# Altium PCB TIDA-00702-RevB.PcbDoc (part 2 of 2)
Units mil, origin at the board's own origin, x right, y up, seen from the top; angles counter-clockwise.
Board outline 3789.41 x 3228.35 mil, 2 copper layers (Top Layer, Bottom Layer), stack 62 mil thick; 129 components, 54 nets, 298 pads, 91 vias.
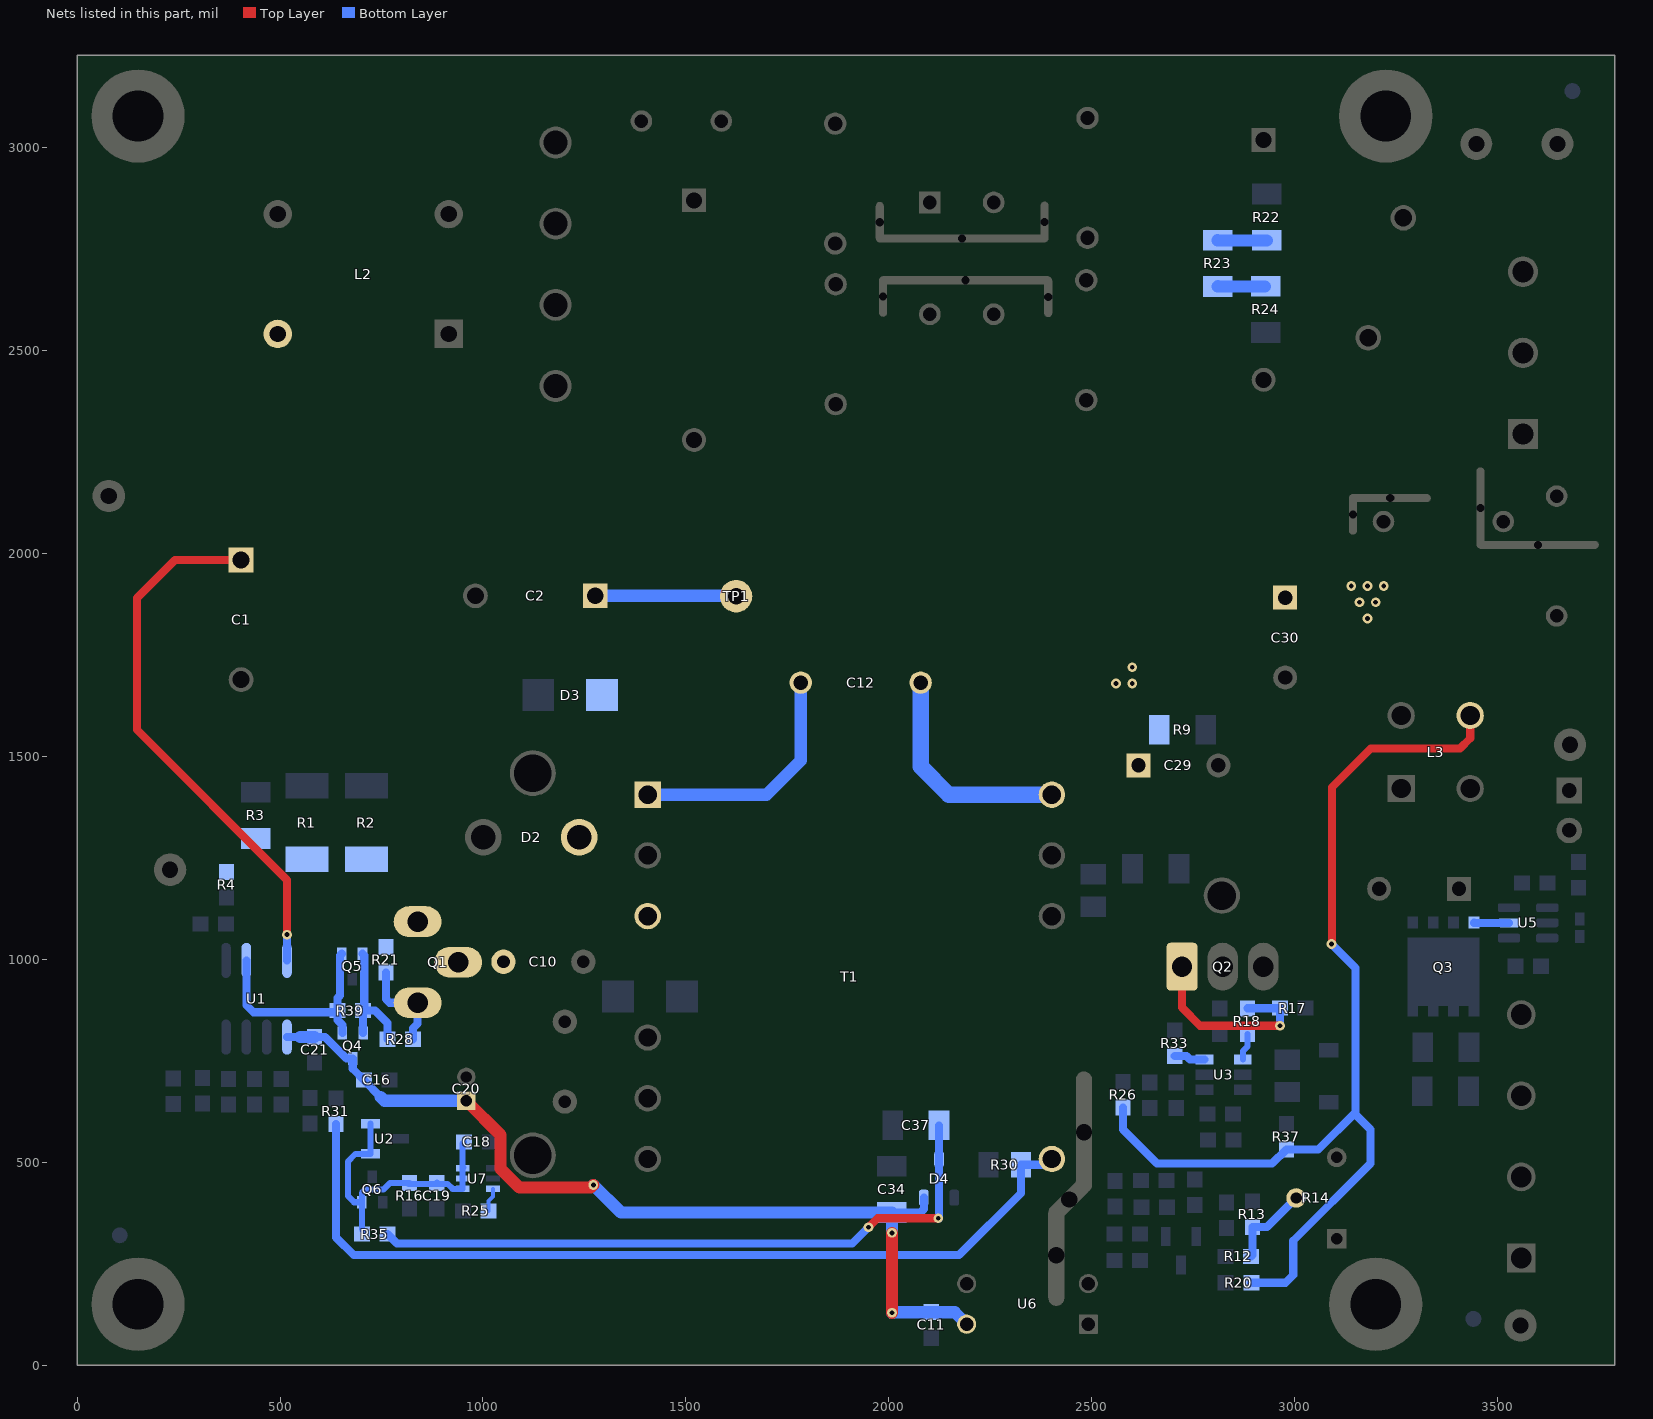
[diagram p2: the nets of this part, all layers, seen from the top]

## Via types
v1: diameter 24, hole 12, Top Layer to Bottom Layer, tented both sides, 82 vias
v2: diameter 20, hole 10, Top Layer to Bottom Layer, 9 vias

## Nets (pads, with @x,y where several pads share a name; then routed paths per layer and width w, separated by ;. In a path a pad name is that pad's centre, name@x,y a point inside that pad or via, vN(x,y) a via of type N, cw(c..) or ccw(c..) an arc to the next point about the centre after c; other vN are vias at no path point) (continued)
NetQ1_1: Q1.1 R21.2 R28.2 | length 241.8
  Bottom Layer w20: R21.2@761,967.5 761,902 770,893 Q1.1@839,893 839,841.47 827.78,830.24 R28.2@827.78,803.04
NetQ1_3: Q1.3 R1.2 R2.1 R3.2 R4.2 R21.1
NetQ2_1: Q2.1 R17.1 R18.2 | length 485.2
  Top Layer w20: Q2.1@2723,982 2723,881 2767.5,836.5 v1(2964.5,836.5)
  Bottom Layer w20: R18.2@2884,879.5 2964,879.5 R17.1@2964.5,880 v1(2964.5,836.5)
NetQ3_4: Q3.4 U5.5 | length 86.3
  Bottom Layer w20: Q3.4@3442.38,1090.34 3442.72,1090 U5.5@3528.51,1090
NetQ4_1: Q4.1 Q5.1 R39.1 U1.6 | length 542.7
  Bottom Layer w20: U1.6@417,997.49 417,887 434.18,869.82 R39.1@637.32,869.82 ; Q5.1@652,1014 647.59,1009.59 647.59,911 641.5,904.91 R39.1@641.5,874 641.5,850.5 653.41,838.59 Q4.1@653.41,818.5
NetQ4_2: Q4.2 Q5.2 R28.1 R39.2 | length 311.7
  Bottom Layer w20: Q5.2@703.18,1014 707.59,1009.59 707.59,877.09 R39.2@704.5,874 ; Q4.2@704.5,818.59 R39.2@704.5,874 ; R28.1@764.78,803.04 764.78,843.22 734,874 R39.2@704.5,874
NetR12_1: R12.1 R13.2 R14.2 | length 211.4
  Bottom Layer w20: R12.1@2892.76,268 2896.27,271.5 R13.2@2896.27,340.5 2932.57,340.5 R14.2@3004.06,412
NetR18_1: R18.1 U3.4 | length 67.8
  Bottom Layer w15: U3.4@2872.71,753.4 2872.71,773.71 2884,785 R18.1@2884,816.5
NetR22_2: R22.2 R23.1 | length 121.1
  Bottom Layer w30: R23.1@2810.64,2772.14 2810.81,2771.97 R22.2@2931.64,2771.97
NetR23_2: R23.2 R24.1 | length 118.5
  Bottom Layer w30: R23.2@2811.81,2659.14 R23.2@2810.64,2657.97 R24.1@2927.47,2657.97
NetR25_1: R25.1 U7.3 | length 59.1
  Bottom Layer w10: R25.1@1013.41,379.98 1013.41,404.74 1024.67,416 U7.3@1024.67,434.39
NetR30_1: R30.1 R31.2 T1.7 | length 2201.1
  Bottom Layer w20: R31.2@637.8,593.99 637.8,314.73 681.53,271 2173.4,271 2326,423.6 R30.1@2326,494 2387.85,494 T1.7@2402.03,508.18
NetR33_1: R33.1 U3.3 | length 76.6
  Bottom Layer w20: R33.1@2705,761.5 2733.9,761.5 2742,753.4 U3.3@2778.22,753.4
TM2: C10.2 D2.1 Q1.2 T1.3
V2.5V: C18.1 C19.2 Q6.2 R16.2 R35.2 U2.1 U2.2 U7.4 U7.5 U7.6 | length 751.6
  Bottom Layer w15: R35.2@707.94,329.13 701.68,335.39 Q6.2@701.68,401.49 ; U2.2@722.83,595.38 U2.1@722.83,520.58 685.86,520.58 667,501.72 667,417 682.51,401.49 Q6.2@701.68,401.49 ; R16.2@817.1,446.48 C19.2@883.27,446.48 ; R16.2@819.27,448.48 770.76,448.48 755.27,432.98 710.27,432.98 701.68,424.39 Q6.2@701.68,401.49 ; C19.2@886.27,449.48 885.77,448.98 C19.2@883.27,446.48 ; U7.6@951.77,487.48 U7.6@949.86,485.57 ; C18.1@953.77,549.98 949.86,546.08 U7.6@949.86,485.57 ; C19.2@883.27,446.48 886.27,446.48 913.04,446.48 925.12,434.39 U7.4@949.86,434.39 U7.5@949.86,459.98 U7.6@949.86,485.57
VCC: C37.1 D4.3 R35.1 | length 1621.4
  Top Layer w20: v1(1950,340) 1972,362 v1(2122,362)
  Bottom Layer w20: R35.1@764.9,323.09 787.99,300 1910,300 v1(1950,340) ; v1@2124,362 D4.3@2124,507.24 2124,590.91 C37.1@2124.09,591
VDCBUS+: C1.1 C2.1 C12.1 D3.1 L2.2 T1.1 TP1.1 U1.8 | length 2300.1
  Top Layer w20: C1.1@404,1984.64 240.64,1984.64 147,1891 147,1566 517,1196 v1(517,1061)
  Bottom Layer w20: U1.8@517,997.49 v1(517,1061)
  Bottom Layer w30: C2.1@1276.64,1896 1616,1896 TP1.1@1626,1906 ; T1.1@1405.97,1405.82 1698.82,1405.82 1783.36,1490.36 C12.1@1783.36,1682
VDD: C11.1 C16.1 C20.1 C21.1 C34.1 D4.2 Q4.3 U1.1 U6.4 | length 2293.4
  Top Layer w30: C20.1@959,651.47 1043.54,566.93 1043.54,484.03 1090.09,437.48 1265.48,437.48 v1(1272,444) ; v1(2008,129) v1(2008,326)
  Bottom Layer w20: U1.1@517,808.51 549.51,808.51 ; C21.1@585,808.5 610.39,808.5 663.39,755.5 Q4.3@679,755.5 679,730.5 C16.1@706.5,703 706.5,702.15 747.83,660.83 ; C34.1@2008,375.91 2077.91,375.91 2086.6,384.6 D4.2@2086.6,412.76
  Bottom Layer w30: 549.53,808.5 C21.1@585,808.5 ; 747.83,660.83 757.18,651.47 C20.1@959,651.47 ; v1(1272,444) 1340.09,375.91 C34.1@2008,375.91 v1(2008,326) ; v1(2008,129) 2009.5,130.5 C11.1@2105,130.5 2162.5,130.5 U6.4@2192,101
VOUT: C12.2 C29.1 C30.1 L3.4 R9.2 R20.1 R26.1 R37.1 T1.12 | length 3155.9
  Top Layer w20: v1(3091,1038) 3091,1036 3092.16,1037.16 3092.16,1424.16 3188,1520 3408,1520 3433.04,1545.04 L3.4@3433.04,1600.96
  Bottom Layer w20: R26.1@2577.47,634.5 2577.47,580.53 2661.5,496.5 2945,496.5 R37.1@2980,531.5 3058.5,531.5 3150,623 ; R20.1@2893.5,203 2978,203 2997,222 2997,306.5 3187,496.5 3187,581 3150,618 3150,623 ; v1(3091,1038) 3150,979 3150,623
  Bottom Layer w40: C12.2@2078.64,1682 2078.64,1475.36 2148.18,1405.82 T1.12@2402.03,1405.82
  other v1: 2560,1680 2600,1680 2600,1720 3180,1840 3160,1880 3200,1880 3140,1920 3180,1920 3220,1920
pads on no net: FID1.1 FID2.1 FID3.1 H1.1 H2.1 H3.1 H4.1 HS2.1@1123,1459.06 R14.1 T1.2 T1.8 T1.9 T1.11

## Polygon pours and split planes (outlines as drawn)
GND-3 on Bottom Layer "Bottom Layer-No Net" (solid, remove dead copper, pour order 72): 3102,1325 3102,1359 3102,1443 3114,1455 3235,1455 3296,1455 3301,1450 3302,1449 3302,1422 3302,1246 3279,1223 3249,1193 3249,842 3268,823 3342,823 3352,813 3352,619 3448,523 3592,523 3632,483 3632,243 3603,214 3523,214 3345,214 3299,260 3218,341 3218,394 3218,615 3180.26,652.74 3166,667 3166,719 3166,1020 3102,1084 3102,1098 3102,1326
NetC17_1 on Bottom Layer "Bottom Layer-No Net" (solid, remove dead copper, pour order 70): 3274,1078 3274,1163 3284,1173 3325,1214 3384,1214 3401,1231 3401,1268 3401,1438 3423,1460 3452,1460 3511,1460 3513,1458 3526,1445 3526,1388 3526,1213 3511,1198 3409,1096 3409,1079 3409,1077 3406,1074 3405.72,1073.72 3394.72,1073.72 3276.28,1073.72 3274,1076
GND-2 on Bottom Layer "Bottom Layer-No Net" (solid, remove dead copper, pour order 68): 2531,56 2531,835 2552,856 2847,856 2860,869 2883,892 2883,1046.35 2883,1072 2849,1106 2767,1188 2742,1188 2692,1188 2679,1201 2679,1266 2705,1292 2753,1340 2753,1401 2753,1607 2878,1732 3021,1732 3277,1732 3298,1711 3298,1612 3298,1583 3289,1574 3278,1563 3266,1563 3076,1563 3063,1550 3063,1547 3063,975 3125,913 3124,912 3124,319 3032,227 3032,67 3006,41 2546,41
VOUT on Bottom Layer "Bottom Layer-No Net" (solid, remove dead copper, pour order 66): 2368,1533 2368,1381 2382,1367 2632,1367 2668,1367 2694,1393 2694,1489 2694,1628 2861,1795 3144,1795 3234,1795 3251,1812 3251,1932 3236,1947 3139,1947 2781,1947 2736,1902 2368,1534
GND on Bottom Layer "Bottom Layer-No Net" (solid, remove dead copper, pour order 64): 549,1659 549,1633 549,1629 551,1627 553,1625 553,1624 553,1580 549,1576 548,1575 548,1564 548,1497 551,1494 564.87,1480.13 784,1480.13 793.13,1480.13 797,1484 797,1544 797,1613 858,1674 858,1695 854,1699 844,1709 615,1709 561,1709 549,1697
GND on Bottom Layer "Bottom Layer-No Net" (solid, remove dead copper, pour order 63): 72,2906 516,2906 527,2895 533,2889 533,2861 533,2794 522,2783 517,2778 459,2778 306,2778 222,2694 222,1893 272,1843 307,1808 419,1808 837,1808 955,1926 1005,1926 1019,1912 1019,1889 1019,1871 1019,1835 813,1629 613,1629 118,1629 58,1689 46,1701 46,1996 46,2880
VDCBUS+ on Bottom Layer "Bottom Layer-No Net" (solid, remove dead copper, pour order 62): 367,2555 367,2093 367,1997 367,1955 376,1946 384,1938 433,1938 741,1938 848,2045 1108,2045 1204,1949 1246,1907 1246,1879 1246,1621 1281,1586 1364,1503 1364,1415 1364,1376 1370,1370 1373,1367 1513,1367 1515,1367 1538,1390 1539,1391 1539,1436 1539,1760 1518,1781 1463,1836 1380,1836 1340,1836 1313,1863 1310,1866 1310,2024 1178,2156 1146,2188 954,2188 578,2188 558,2208 558,2563 538,2583 437,2583 395,2583
NetBR1_1 on Bottom Layer "Bottom Layer-No Net" (solid, remove dead copper, pour order 60): 1173,2372 1200,2372 1204,2376 1219,2391 1219,2404 1219,2441 1209,2451 1208,2452 1178,2452 1027,2452 998,2481 992,2487 992,2572 979,2585 853,2585 840,2572 840,2555 840,2353 856,2337 863,2330 979,2330 1072,2330 1114,2372
NetBR1_4 on Bottom Layer "Bottom Layer-No Net" (solid, remove dead copper, pour order 61): 1173,3054 1200,3054 1204,3050 1219,3035 1219,3022 1219,2985 1209,2975 1208,2974 1178,2974 1027,2974 998,2945 992,2939 992,2846 992,2816 976,2800 920,2800 879,2800 862,2800 858,2800 854,2800 841,2813 840,2814 840,2871 840,3073 856,3089 863,3096 979,3096 1072,3096 1114,3054
NetBR1_2 on Bottom Layer "Bottom Layer-No Net" (solid, remove dead copper, pour order 57): 1148,2652 1224,2652 1374,2652 1396,2630 1460.36,2565.64 1460.36,2485 1460.36,2352.64 1485,2328 1553,2328 1758,2328 1794,2364 1829,2399 1855,2399 1947,2399 1985,2437 2046,2498 2046,2577 2046,2603 2055,2612 2061,2618 2094,2618 2121,2618 2126,2613 2133,2606 2133,2584 2133,2438 1996,2301 1974,2279 1855,2279 1849,2279 1804,2234 1777,2207 1534,2207 1427,2207 1345,2289 1344,2290 1344,2430 1344,2484 1255,2573 1183,2573 1146,2573 1135,2584 1135,2642 1145,2652
NetC4_1 on Bottom Layer "Bottom Layer-No Net" (solid, remove dead copper, pour order 56): 1485,2899 1482,2896 1482,2872 1482,2843 1493,2832 1545,2832 1661,2948 1706,2993 1787,2993 1919,2993 2073,2839 2077,2835 2125,2835 2131,2841 2131,2953 1969,3115 1866,3115 1583,3115 1556,3088 1554,3086 1554,2968 1492,2906
NetQ1_3 on Bottom Layer "Bottom Layer-No Net 1" (solid, remove dead copper, pour order 45): 724.23,1067.77 724.23,1017.77 733,1009 792.89,1009 798,1014.11 798,1051 802,1055 879,1055 899,1075 899,1160 879,1180 799.24,1180 795,1184.24 795,1319 781,1333 348,1333 337,1322 337,1203 345,1195 597,1195
GND on Bottom Layer "Bottom Layer-No Net 6" (solid, remove dead copper, pour order 53): 87,1576 49,1538 49,1042 63,1028 280,1028 303.5,1051 304,1337 342,1376 775,1376 797,1398 797,1544 765,1576
GND on Bottom Layer "Bottom Layer-No Net 1" (solid, remove dead copper, pour order 46): 996,571 996,514 996,467 1000,463 1010,453 1032,453 1163,453 1174,464 1180,470 1180,512 1180,552 1169,563 1159,573 1132,573 1000,573 996,569
NetBR1_3 on Bottom Layer "Bottom Layer-No Net 1" (solid, remove dead copper, pour order 44): 1242,2852 1342,2952 1342,3089 1353,3100 1427,3100 1436,3091 1436,2939 1268,2771 1149,2771 1138,2782 1138,2840 1150,2852
TM2 on Bottom Layer "Bottom Layer-No Net 2" (solid, remove dead copper, pour order 37): 914.39,1028.04 899.04,1028.04 880,1009 880,969 893,956 1053,956 1189,1092 1337,1092 1356,1073 1438,1073 1445,1080 1445,1138 1438,1145 1360,1145 1289,1216 1289,1327 1269,1347 1211,1347 1191,1327 1191,1273 946,1028 931,1028
GND-3 on Bottom Layer "Bottom Layer-No Net 7" (solid, remove dead copper, pour order 39): 3594,1098 3584,1088 3584,1003 3584,970 3590,964 3592,962 3636.78,962 3718,962 3727,971 3731,975 3731,1041 3731,1071.26 3724.26,1078 3699,1078 3678,1078 3670,1086 3653,1103 3646,1103 3599,1103 3594,1098
NetC32_1 on Bottom Layer "Bottom Layer-No Net 8" (solid, remove dead copper, pour order 43): 3272,1049 3272,860 3276,856 3279,853 3381,853 3386,853 3393,846 3398,841 3398,816 3398,641 3406,633 3411.64,627.36 3466.49,627.36 3610.36,627.36 3625,642 3629,646 3629,797 3629,894 3618,905 3617,906 3561,906 3491,906 3477,920 3469,928 3469,1009 3469,1036 3451,1054 3297,1054 3277,1054 3272,1049
GND on Bottom Layer "Bottom Layer-No Net 1" (solid, remove dead copper, pour order 51): 38,401 56,383 177,383 312,248 312,78 339,51 804,51 810,45 2082.5,45 2107,69.5 2107,522.3 2107,494 2050,551 2045.5,555.5 2045.5,636.5 2030,652 1978,652 1873,547 1185,547 1155.95,576.05 1148.93,576.07 1105,576 1077.64,576.07 1062,590 1062,696 1010,748 808,748 725.59,830.41 725.59,915.41 715,926 410,926 380,956 380,1103.27 355.27,1128 59,1128 38,1107
NetC28_2 on Bottom Layer "Top Layer-No Net 3" (solid, remove dead copper, pour order 48): 2363,1140 2363,961 2363,946 2363,935 2368,930 2385,913 2438,913 2615.99,913 2626.13,923.15 2638,935.01 2638,1031 2638,1047 2653,1062 2732,1062 2769,1062 2782,1049 2787,1044 2787,1032 2787,939.15 2803,923.15 2803.15,923 2845,923 2860,938 2861,939 2861,973 2861,1053 2821.95,1092.05 2756,1158 2727,1158 2381,1158 2363,1140
NetF1_2 on Bottom Layer "Bottom Layer-No Net" (solid, remove dead copper, pour order 38): 3610,3054.65 3607,3051.65 3607,2969.65 3607,2785.65 3592,2770.65 3576,2754.65 3555,2754.65 3527,2754.65 3524,2751.65 3517,2744.65 3517,2722.65 3517,2669.65 3522,2664.65 3531,2655.65 3564,2655.65 3720,2655.65 3733,2668.65 3738,2673.65 3738,2794.65 3738,3052.65 3730,3060.65 3616,3060.65
GNDE on Bottom Layer "Bottom Layer-No Net" (solid, remove dead copper, pour order 42): 3520,2329.65 3520,2168.65 3499,2147.65 3489,2137.65 3489,2083.65 3489,2066.65 3494,2061.65 3502,2053.65 3530,2053.65 3560,2053.65 3561,2053.65 3568,2060.65 3572,2064.65 3572,2093.65 3572,2101.65 3580,2109.65 3581,2110.65 3631,2110.65 3681,2110.65 3684,2113.65 3685,2114.65 3685,2143.65 3685,2309.65 3685,2321.65 3674,2332.65 3672,2334.65 3585,2334.65 3524,2334.65 3520,2330.65
NetC3_1 on Bottom Layer "M9 Title Sheet-No Net" (solid, remove dead copper, pour order 54): 3421,3051.65 3410,3040.65 3410,3022.65 3410,2980.65 3401,2971.65 3288,2858.65 3270,2858.65 3255,2858.65 3243,2870.65 3203,2910.65 3170,2910.65 3096,2910.65 2950,3056.65 2894,3056.65 2850,3056.65 2846,3060.65 2791,3115.65 2492,3115.65 2394,3115.65 2236,2957.65 2231,2952.65 2231,2883.65 2231,2847.65 2240,2838.65 2242,2836.65 2278,2836.65 2305,2836.65 2309,2840.65 2320,2851.65 2320,2879.65 2320,2888.65 2370,2938.65 2417,2985.65 2747,2985.65 2873,2859.65 2964,2859.65 3045,2778.65 3219,2778.65 3235,2794.65 3237,2796.65 3248,2796.65 3300,2796.65 3311,2785.65 3316,2780.65 3380,2780.65 3490,2890.65 3490,3038.65 3477,3051.65
GND-3 on Top Layer "Bottom Layer-No Net" (solid, remove dead copper, pour order 71): 3102,1325 3102,1359 3102,1443 3114,1455 3235,1455 3296,1455 3301,1450 3302,1449 3302,1422 3302,1246 3279,1223 3249,1193 3249,842 3268,823 3342,823 3352,813 3352,619 3448,523 3592,523 3632,483 3632,243 3603,214 3523,214 3345,214 3299,260 3218,341 3218,394 3218,615 3180.26,652.74 3166,667 3166,719 3166,1020 3102,1084 3102,1098 3102,1326
NetC17_1 on Top Layer "Bottom Layer-No Net" (solid, remove dead copper, pour order 69): 3274,1078 3274,1163 3284,1173 3325,1214 3384,1214 3401,1231 3401,1268 3401,1438 3423,1460 3452,1460 3511,1460 3513,1458 3526,1445 3526,1388 3526,1213 3511,1198 3409,1096 3409,1079 3409,1077 3406,1074 3405.72,1073.72 3394.72,1073.72 3276.28,1073.72 3274,1076
GND-2 on Top Layer "Bottom Layer-No Net" (solid, remove dead copper, pour order 67): 2531,56 2531,835 2552,856 2847,856 2860,869 2883,892 2883,1046.35 2883,1072 2849,1106 2767,1188 2742,1188 2692,1188 2679,1201 2679,1266 2705,1292 2753,1340 2753,1401 2753,1607 2878,1732 3021,1732 3277,1732 3298,1711 3298,1612 3298,1583 3289,1574 3278,1563 3266,1563 3076,1563 3063,1550 3063,1547 3063,975 3125,913 3124,912 3124,319 3032,227 3032,67 3006,41 2546,41
VOUT on Top Layer "Bottom Layer-No Net" (solid, remove dead copper, pour order 65): 2368,1532 2368,1381 2382,1367 2668,1367 2694,1393 2694,1627 2862,1795 3363,1795 3386,1772 3389,1769 3389,1648 3389,1586 3398,1577 3407,1568 3449,1568 3485,1568 3494,1577 3504,1587 3504,1673 3504,1909 3477,1936 3467,1946 3426,1946 2781,1946 2755,1920 2368,1533
NetBR1_4 on Top Layer "Bottom Layer-No Net" (solid, remove dead copper, pour order 58): 1173,3054 1200,3054 1204,3050 1219,3035 1219,3022 1219,2985 1209,2975 1208,2974 1178,2974 1027,2974 998,2945 992,2939 992,2846 992,2816 976,2800 920,2800 879,2800 862,2800 858,2800 854,2800 841,2813 840,2814 840,2871 840,3073 856,3089 863,3096 979,3096 1072,3096 1114,3054
NetBR1_1 on Top Layer "Bottom Layer-No Net" (solid, remove dead copper, pour order 59): 1173,2372 1200,2372 1204,2376 1219,2391 1219,2404 1219,2441 1209,2451 1208,2452 1178,2452 1027,2452 998,2481 992,2487 992,2572 979,2585 853,2585 840,2572 840,2555 840,2353 856,2337 863,2330 979,2330 1072,2330 1114,2372
GND on Top Layer "Bottom Layer-No Net 1" (solid, remove dead copper, pour order 52): 612,1514 612,928 608,924 608,911 621,898 718,898 733,913 733,1167 798,1232 798,1515 788,1525 623,1525
NetBR1_2 on Top Layer "Bottom Layer-No Net 1" (solid, remove dead copper, pour order 49): 1135,2642 1135,2584 1146,2573 1202,2573 1256,2573 1285,2544 1344,2485 1344,2290 1427,2207 1550,2207 1558,2207 1564,2213 1564,2241 1564,2317 1558,2323 1553,2328 1536,2328 1484,2328 1460,2352 1460.36,2352.36 1460.36,2400.43 1460.36,2565.64 1377,2649 1374,2652 1360,2652 1145,2652
NetBR1_3 on Top Layer "Bottom Layer-No Net 1" (solid, remove dead copper, pour order 41): 1242,2852 1342,2952 1342,3089 1353,3100 1427,3100 1436,3091 1436,2939 1268,2771 1149,2771 1138,2782 1138,2840 1150,2852
NetC32_1 on Top Layer "Bottom Layer-No Net 8" (solid, remove dead copper, pour order 40): 3272,1049 3272,860 3276,856 3279,853 3381,853 3386,853 3393,846 3398,841 3398,816 3398,641 3406,633 3411.64,627.36 3466.49,627.36 3610.36,627.36 3625,642 3629,646 3629,797 3629,894 3618,905 3617,906 3561,906 3491,906 3477,920 3469,928 3469,1009 3469,1036 3451,1054 3297,1054 3277,1054 3272,1049
GND on Top Layer "Bottom Layer-No Net 1" (solid, remove dead copper, pour order 50): 38,401 56,383 176,383 312,247 312,78 339,51 804,51 810,45 2082.5,45 2113,75.5 2113,308 2082,339 1285,339 1181,443 1181,544 1149,576 1077.64,576.07 1062,590 1062,696 1010,748 808,748 725.59,830.41 725.59,915.41 715,926 410,926 380,956 380,1103.27 355.27,1128 59,1128 38,1107
NetC28_2 on Top Layer "Top Layer-No Net 3" (solid, remove dead copper, pour order 47): 2363,1140 2363,961 2363,946 2363,935 2368,930 2385,913 2438,913 2615.99,913 2626.13,923.15 2638,935.01 2638,1031 2638,1047 2653,1062 2732,1062 2769,1062 2782,1049 2787,1044 2787,1032 2787,939.15 2803,923.15 2803.15,923 2845,923 2860,938 2861,939 2861,973 2861,1053 2821.95,1092.05 2756,1158 2727,1158 2381,1158 2363,1140
NetC3_2 on Top Layer "M9 Title Sheet-No Net" (solid, remove dead copper, pour order 55): 2230,2616.65 2225,2611.65 2225,2510.65 2225,2497.65 2311,2411.65 2389,2333.65 2401,2321.65 2567,2321.65 2818,2321.65 2866,2369.65 2893,2396.65 2932,2396.65 2956,2396.65 2973,2379.65 3056,2379.65 3175,2498.65 3221,2498.65 3266,2453.65 3376,2453.65 3594,2453.65 3605,2464.65 3605,2518.65 3591,2532.65 3495.85,2532.65 3450.85,2577.65 3440,2577.65 3232,2577.65 3218,2563.65 3103,2563.65 3011,2471.65 2800,2471.65 2451,2471.65 2294,2628.65 2264,2628.65 2242,2628.65

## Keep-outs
Keep-Out Layer:
  lines w10: 25,25 3746,25 3746,3196 25,3196 25,25

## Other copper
Top Layer:
  pour cut-out: 1070,579 1068,577 1068,485 1095,458 1180,458 1186,464 1186,569 1176,579
  text ".Layer_Name" at -358,-858.49 h60
Bottom Layer:
  pour cut-out: 724.23,1028.49 734.99,1038.75 724.23,1049.51
  pour cut-out: 3436,1125 3408.99,1125 3403,1119.01 3403,1082 3395,1074 3417,1074 3428,1085 3428,1117
  text ".Layer_Name" at -358,-858.49 h60

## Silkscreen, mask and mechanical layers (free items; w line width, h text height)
Top Overlay:
  circle w6: c2497,2317 r7
  circle w6: c2661.78,898 r9.22
  circle w6: c939.78,877 r9.22
  circle w6: c3618,1436 r7
  circle w6: c2923,3093.65 r7.07
  circle w6: c3117,2483 r6.32
  circle w10: c3585,2174.65 r8.25
  circle w6: c2526.32,3124.1 r7
  circle w6: c1904.32,3110.1 r7
  circle w6: c1888,2304.64 r7
  circle w6: c1680.46,2876.68 r7
  circle w6: c3683,1809 r6.32
  circle w6: c3184,2045 r6.32
  circle w6: c1710,1678 r7.21
  circle w6: c1288,3170 r8.06
  text ".PRJ_Number" at 515,143 h60
  text ".PCB_Rev" at 1166,141 h60
  text "-" at 1107,139 h60
  text ".Layer_Name" at -358,-858.49 h60
Bottom Overlay:
  circle w6: c1049.27,501.98 r3.16
  circle w6: c680.27,515.98 r4.12
  circle w6: c2746.47,653 r5
  circle w6: c3229,1096 r7.28
  circle w6: c545,767 r7.07
  circle w6: c2664,351 r5.39
  lines w6: 613,1013 613,947 622,938 622,906 ; 2685,535 2693,527 2693,501 2703,491 2719,491 2719,457.93 2722,454.93 2722,426 2714.25,418.25 2714.25,416.2 ; 2783.99,916 2845,916 2853.02,907.98 2856.8,907.98 ; 2878.45,527.8 2878.45,513.55 2893,499 ; 2922,778 2922,786 2928,792 ; 3008,798 3010.53,798 3016.53,804 3019,804 3022,807
  text ".Layer_Name" at -358,-858.49 h60
Top Paste:
  text ".Layer_Name" at -358,-858.49 h60
Bottom Paste:
  text ".Layer_Name" at -358,-858.49 h60
Top Solder:
  text ".Layer_Name" at -358,-858.49 h60
  text ".Layer_Name" at -358,-858.49 h60
Bottom Solder:
  text ".Layer_Name" at -358,-858.49 h60
Drill Guide:
  text ".Layer_Name" at -358,-858.49 h60
M1 Board Outline:
  the board outline again, w10
M2 Board Dimensions:
  rectangle: -810,-410.5 -435,-285.5
  rectangle: -935,-285.5 -810,-160.5
  lines w7: -935,-285.5 65,-285.5 ; -810,-410.5 -810,-160.5 ; -685,-410.5 -685,-160.5 ; -435,-410.5 -435,-160.5 ; -185,-410.5 -185,-160.5 ; -935,-410.5 -935,-160.5 65,-160.5 65,-410.5 -935,-410.5
M3 3D STEP Top:
  text ".Layer_Name" at -358,-858.49 h60
M4 3D STEP Bottom:
  text ".Layer_Name" at -358,-858.49 h60
M5 Assembly Top:
  circle w6: c2101.26,2865.45 r10.33
  circle w6: c3181.69,2532.02 r10.77
  circle w6: c3561,2294 r11.18
  circle w7.87: c2711,1478 r196.85
  circle w7.87: c2978,1792 r196.85
  circle w7.87: c3307,1174 r196.85
  circle w7.87: c3676,1412 r5.83
  circle w7.87: c2719,981 r10.44
  circle w6: c2927,3012.65 r10.77
  circle w6: c3241,2073.72 r10.77
  circle w6: c3649,1866.72 r10.77
  circle w6: c2490,2372.09 r10.77
  circle w6: c2493,3067.36 r10.77
  circle w6: c1871,3053.36 r10.77
  circle w6: c1872,2362.09 r10.77
  circle w6: c1523.36,2864.51 r10.77
  circle w6: c1389,3067.72 r10.77
  circle w6: c918.63,2535.09 r10.77
  circle w6: c1786.36,1675.72 r10.77
  lines w6: 2543,1603 2581,1603 ; 2560,1583 2560,1623 ; 2951,2015 2989,2015 ; 2969,1994 2969,2034 ; 3526,1171 3564,1171 ; 3543,1151 3543,1191
  lines w10: -1227,-930.17 5373,-930.17 ; -1227,-726.83 5375,-726.83 ; -1227,-523.5 -1227,-1133.5 2778,-1133.5 5375,-1133.5 5375,-523.5 -1226.5,-523.5 -1226.5,-1133.5 349,-1133.5 ; 1238,-1133.5 1238,-523.5 ; 2505,-726.83 2505,-523.5 ; 3345,-726.83 3345,-523.5 ; 3967,-1140 3967,-937.17
  text "COMPONENTS MARKED 'DNP' SHOULD NOT BE POPULATED." at 218.5,-318.5 h60
  text "ASSEMBLY VARIANT:" at 218,-434 h60
  text ".VariantName" at 1254,-434 h60
  text "PCB VIEWED FROM TOP SIDE" at -1163.5,-655.67 h60
  text "BOARD #:" at 1313,-655.67 h60
  text ".PRJ_Number" at 1858.5,-655.67 h60
  text "REV:" at 2703,-655.67 h60
  text ".PCB_Rev" at 2994.5,-655.67 h60
  text "SVN REV:" at 3541,-655.67 h60
  text ".VersionControl_RevNumber" at 4047,-655.67 h35
  text ".Layer_Name" at -347,-851 h60
  text "IGNORE ->" at -1163.5,-858.49 h60
  text "PLOT NAME =" at -1163.5,-1064.34 h60
  text ".plot_File_Name" at -358,-1064.34 h60
  text "GENERATED    :" at 1315,-1064.34 h60
  text ".Print_Date" at 2184.5,-1064.34 h60
  text ".Print_Time" at 2913.5,-1064.34 h60
  text "TEXAS INSTRUMENTS" at 4178,-1064.34 h60
M6 Assembly Bottom:
  circle w6: c2186,415 r6
  circle w6: c2682,293 r6.08
  circle w6: c694,564 r8.06
  circle w7.87: c3658,1149 r3.16
  circle w7.87: c516.4,850 r6.4
  circle w7.87: c627,1026 r7.81
  circle w7.87: c629,830 r6.4
  circle w7.87: c758.39,374 r5.39
  lines w10: -1227.5,-727.33 5374.5,-727.33 ; -1225.5,-930.67 5374.5,-930.67 ; 180.5,-1140.5 180.5,-937.67 ; 802.5,-727.33 802.5,-524 ; 1642.5,-727.33 1642.5,-524 ; 2909.5,-1134 2909.5,-524 ; 3798.5,-1134 5374,-1134 5374,-524 -1227.5,-524 -1227.5,-1134 1369.5,-1134 5374.5,-1134 5374.5,-524
  text "COMPONENTS MARKED 'DNP' SHOULD NOT BE POPULATED." at 5167,-318 h60
  text ".VariantName" at 4123,-434 h60
  text "ASSEMBLY VARIANT:" at 5162,-434 h60
  text ".VersionControl_RevNumber" at 100.5,-656.17 h35
  text "SVN REV:" at 606.5,-656.17 h60
  text ".PCB_Rev" at 1153,-656.17 h60
  text "REV:" at 1444.5,-656.17 h60
  text ".PRJ_Number" at 2289,-656.17 h60
  text "BOARD #:" at 2834.5,-656.17 h60
  text "PCB VIEWED FROM BOTTOM SIDE" at 5311,-656.17 h60
  text "IGNORE ->" at 1612.85,-858.49 h60
  text ".Layer_Name" at 958,-863 h60
  text "TEXAS INSTRUMENTS" at -30.5,-1064.84 h60
  text ".Print_Time" at 1234,-1064.84 h60
  text ".Print_Date" at 1963,-1064.84 h60
  text "GENERATED    :" at 2832.5,-1064.84 h60
  text ".plot_File_Name" at 4505.5,-1064.84 h60
  text "PLOT NAME =" at 5311,-1064.84 h60
M9 Title Sheet:
  drawing of 58 lines, arcs and shapes, not listed
  text "1" at -195.16,8036.5 h70
  text "2" at 2300.5,8036.5 h70
  text "3" at 4789.84,8036.5 h70
  text "4" at 7296.51,8036.5 h70
  text "5" at 9795.5,8036.5 h70
  text "6" at 12300.5,8036.5 h70
  text "A" at -1351.5,6893.5 h70
  text "A" at 13448.5,6893.5 h70
  text "B" at -1351.5,4513.5 h70
  text "B" at 13448.5,4513.5 h70
  text "C" at -1351.5,2138.5 h70
  text "C" at 13448.5,2138.5 h70
  text "PROJECT TITLE:" at 10408.5,277.5 h45
  text ".PRJ_Title" at 10458.5,144.17 h70
  text "DESIGNED FOR:" at 10408.5,-23.5 h45
  text ".PRJ_Customer" at 10458.5,-163.5 h70
  text "D" at -1351.5,-231.5 h70
  text "D" at 13448.5,-231.5 h70
  text "FILE NAME:" at 10408.5,-323.5 h45
  text ".PCB_File_Name_No_Path" at 10458.5,-443.5 h70
  text "Texas Instruments (TI) and/or its licensors do not warrant the accuracy or completeness of this specification" at 5439,-605.34 h45
  text "ENGINEER:" at 10408.5,-613.5 h45
  text "LAYOUT BY:" at 11913.5,-613.5 h45
  text "or any information contained therein. TI and/or its licensors do not warrant that this design will meet" at 5394.01,-718 h45
  text ".PRJ_Engineer" at 10458.5,-768.49 h70
  text ".PCB_Layout" at 11964,-768.49 h70
  text "the specifications, will be suitable for your application or fit for any particular purpose, or will operate in" at 5394.01,-830.67 h45
  text "ALTIUM DESIGNER VERSION:" at 11913.5,-923.5 h45
  text "an implementation. TI and/or its licensors do not warrant that the design is production worthy. You should" at 5394.01,-943.33 h45
  text "completely validate and test your design implementation to confirm the system functionality for your application." at 5439,-1056 h45
  text ".print_Scale" at 10458.5,-1056.83 h70
  text ".Application_BuildNumber" at 11964,-1056.83 h70
  text "1" at -195.16,-1263.5 h70
  text "2" at 2300.5,-1263.5 h70
  text "3" at 4789.84,-1263.5 h70
  text "4" at 7296.51,-1263.5 h70
  text "5" at 9795.5,-1263.5 h70
  text "6" at 12300.5,-1263.5 h70
M10 Fab Notes:
  drawing of 228 lines, arcs and shapes, not listed
  text "DESIGN INFORMATION" at 11450.02,6802 h60
  text "(REFER ALSO ARRAY/PANEL PROFILING INFORMATION)" at 11088.46,6640.29 h60
  text "BOARD SIZE" at 10402.46,6636 h60
  text "96.25 MM" at 10864.78,6508.18 h60
  text "X" at 11370.46,6508.18 h60
  text "82 MM" at 11601.78,6508.18 h60
  text "Number of Layers :" at 10805.46,6311 h60
  text "2" at 11900.27,6301 h60
  text "MIN. TRACK WIDTH:" at 10805.46,6172 h60
  text "10" at 11901.7,6172 h60
  text "MIL" at 12056.46,6172 h60
  text "MIN. CLEARANCE:" at 10805.46,6040 h60
  text "MIL" at 12056.46,6040 h60
  text "8" at 11893,6034 h60
  text "10" at 11884,5913 h60
  text "MIN. VIA DRILL SIZE:" at 10805.46,5908 h60
  text "MIL" at 12056.46,5908 h60
  text "MINIMUM ANNULAR RING" at 10476.23,5762 h60
  text "EXTERNAL" at 12497,5760 h60
  text "0.110mm (4.37 MIL)" at 11490,5759 h60
  text "PER" at 10676.23,5644 h60
  text "IPC-D-275 CLASS 2 LEVEL C" at 10896.23,5644 h60
  text "MIL, HOLES" at 12384.46,5531.71 h60
  text "+/-" at 11992,5531 h60
  text "+/-" at 12846,5531 h60
  text "REGISTRATION TOLERANCES:" at 10476.23,5526 h60
  text "METAL" at 11676,5526 h60
  text "5" at 12252.2,5526 h60
  text "3" at 13085.2,5526 h60
  text "MIL" at 13201.46,5526 h60
  text "MATERIAL:" at 10401.46,5316.54 h60
  text "FR-4 High Tg" at 11387.9,5176.21 h60
  text "FR-408" at 10822.46,5167.64 h60
  text "OTHER" at 12310.46,5167.64 h60
  text "X" at 11232,5160 h60
  text "63 MIL (1.6mm) +/-10%" at 11142.56,5004.92 h60
  text "THICKNESS:" at 10476.23,5000.64 h60
  text "X" at 11014.4,5000.64 h60
  text "OTHER" at 12427.46,5000.64 h60
  text "TOLERANCE:" at 10476.23,4842.64 h60
  text "X" at 11315.53,4842.64 h60
  text "ANSI IPC-6012 TYPE 3 CLASS 2" at 11502.48,4842.64 h60
  text "OTHER +/-" at 11502.46,4686.64 h60
  text "BOW & TWIST:" at 10476.23,4529.64 h60
  text "X" at 11315.53,4529.64 h60
  text "ANSI IPC-6012 TYPE 3 CLASS 2" at 11502.48,4529.64 h60
  text "OTHER +/-" at 11502.46,4371.13 h60
  text "COPPER THICKNESS (FINISHED):" at 10401.46,4235.64 h60
  text "X" at 12644,4084 h60
  text "1.4MIL (1oz)" at 11281.46,4082.92 h60
  text "2MIL (1.4oz)" at 12048.46,4082.92 h60
  text "2.8MIL (2oz)" at 12775.46,4082.92 h60
  text "OUTER:" at 10758.46,4078.64 h60
  text "1.4MIL (1oz)" at 11281.46,3925.92 h60
  text "2.8MIL (2oz)" at 12048.46,3925.92 h60
  text "N/A" at 12775,3926.29 h60
  text "INNER SIGNAL:" at 10469.38,3921.64 h60
  text "DRILLING:" at 10401.46,3782.64 h60
  text "REFERENCE:" at 10476.23,3665.64 h60
  text "X" at 11124.46,3665.64 h60
  text "AS SHOWN" at 11311.46,3665.64 h60
  text "X" at 12025.46,3665.64 h60
  text "NC_DRILL FILES" at 12162.46,3665.64 h60
  text "PTH MIN COPPER THICKNESS:" at 10476.23,3507.64 h60
  text "X" at 11826.46,3507.64 h60
  text "1MIL" at 11963.46,3507.64 h60
  text "OTHER" at 12460.46,3507.64 h60
  text "BOARD FINISH:" at 10401.46,3348.64 h60
  text "SILKSCREEN:" at 10556.68,3230.64 h60
  text "X" at 11505.46,3230.64 h60
  text "TOP" at 11631.46,3230.64 h60
  text "X" at 12015.46,3230.64 h60
  text "BOTTOM" at 12142.46,3230.64 h60
  text "Notes:" at 4025,3064 h35
  text "SILKSCREEN COLOR:" at 10556.68,3063.64 h60
  text "X" at 11504.42,3063.64 h60
  text "WHITE" at 11631.46,3063.64 h60
  text "OTHER" at 12142.46,3063.64 h60
  text "10mil Drill Vias are not Tented." at 4040,2984 h35
  text "12mil Drill Vias are Tented in both sides." at 4048,2910 h35
  text "SOLDER RESIST COLOR:" at 10556.68,2893.64 h60
  text "X" at 11124.42,2734.44 h60
  text "GREEN" at 11251.46,2734.44 h60
  text "BLUE" at 11842.46,2734.44 h60
  text "OTHER" at 12380.46,2734.44 h60
  text "IMMERSION GOLD (ENIG)" at 11462.46,2545.92 h60
  text "ENEPIG" at 12800,2542.64 h60
  text "SURFACE FINISH:" at 10401.46,2541.64 h60
  text "X" at 11275.51,2541.64 h60
  text "IMM. TIN/SILVER OR EQUIV" at 10731,2384.64 h60
  text "OTHER" at 12162.46,2384.64 h60
  text "ARRAY/PANEL:" at 10401.46,2205.64 h60
  text "CUT AND TRIM PER MECH LAYER 1" at 11462.46,2201.35 h60
  text "N.C. ROUTE" at 11462.46,2049.64 h60
  text "X" at 12141.46,2049.64 h60
  text "V. SCORE" at 12328.46,2049.64 h60
  text "CERTIFICATION:" at 10401.46,1912.64 h60
  text "MATERIALS AND WORKMANSHIP FOR ALL PCBS" at 11126.46,1912.64 h60
  text "TO MEET OR EXCEED THE REQUIREMENTS OF:" at 11126.46,1814.64 h60
  text "X" at 10752.96,1678.13 h60
  text "ANSI IPC-A-600F CLASS ->" at 10891.96,1678.13 h60
  text "X" at 12531.02,1678.13 h60
  text "2" at 12649.96,1678.14 h60
  text "1" at 12334.96,1676.64 h60
  text "3" at 13003.96,1676.64 h60
  text "X" at 10755.02,1518.64 h60
  text "UL 94V-0" at 10891.96,1518.64 h60
  text "X" at 11567.02,1518.64 h60
  text "RoHS" at 11703.96,1518.64 h60
  text "OTHER" at 12348.36,1518.64 h60
  text "PER ORDER" at 12745.42,1518.64 h60
  text "VIA TENTING:" at 11619,1385 h60
  text "X" at 12367,1384 h60
  text "ADDITIONAL REQUIREMENTS:" at 10401.46,1377.64 h60
  text "YES" at 12168.67,1375.92 h60
  text "NO" at 12533.47,1370.69 h60
  text "MICROSECTION:" at 10476.23,1262.64 h60
  text "YES" at 11381.96,1262.64 h60
  text "IMPEDANCE CONTROL:" at 11641,1256 h60
  text "YES" at 12625,1255 h60
  text "X" at 13167,1248 h60
  text "NO" at 13000.47,1237.69 h60
  text "REQUIRED" at 12243.46,1106.49 h60
  text "BARE BOARD ELEC. TEST:" at 10476.23,1103.64 h60
  text "NONE" at 11781.96,1103.64 h60
  text "X" at 12116.46,1103.64 h60
  text "PER ORDER" at 12835.46,1103.64 h60
  text "MANUFACTURER'S UL:" at 10476.23,946.64 h60
  text "RAIL" at 11641.96,942.35 h60
  text "METAL" at 12133.77,942.35 h60
  text "X" at 12509,942 h60
  text "SILK" at 12645.46,942.35 h60
M11 Gerber Information:
  lines w10: -1227,-930.17 5373,-930.17 ; -1227,-726.83 5375,-726.83 ; -1227,-523.5 -1227,-1133.5 2778,-1133.5 5375,-1133.5 5375,-523.5 -1226.5,-523.5 -1226.5,-1133.5 349,-1133.5 ; 1238,-1133.5 1238,-523.5 ; 2505,-726.83 2505,-523.5 ; 3345,-726.83 3345,-523.5 ; 3967,-1140 3967,-937.17
  text "ALL ARTWORK VIEWED FROM TOP SIDE" at -1163.5,-655.67 h60
  text "BOARD #:" at 1313,-655.67 h60
  text ".PRJ_Number" at 1858.5,-655.67 h60
  text "REV:" at 2703,-655.67 h60
  text ".PCB_Rev" at 2994.5,-655.67 h60
  text "SVN REV:" at 3541,-655.67 h60
  text ".VersionControl_RevNumber" at 4047,-655.67 h60
  text "LAYER NAME =" at -1163.5,-858.49 h60
  text "PLOT NAME =" at -1163.5,-1064.34 h60
  text ".plot_File_Name" at -358,-1064.34 h60
  text "GENERATED    :" at 1315,-1064.34 h60
  text ".Print_Date" at 2184.5,-1064.34 h60
  text ".Print_Time" at 2913.5,-1064.34 h60
  text "TEXAS INSTRUMENTS" at 4178,-1064.34 h60
M12 Stackup:
  lines w6: 10305,7617.33 13303,7617.33 ; 10305,7721.73 13303,7721.73 ; 10245,6935 ccw(c10279,6935) 10279,6901 13329,6901 ccw(c13329,6935) 13363,6935 13363,7937 ccw(c13329,7937) 13329,7971 10279,7971 ccw(c10279,7937) 10245,7937 10245,6935
  text "Layer Stack Up Detail for: TIDA-00702.PcbDoc" at 10305,7802.97 h58
  text "Layer" at 10305,7682.73 h24
  text "Gerber" at 10952.48,7682.73 h24
  text "Copper" at 11267.67,7682.73 h24
  text "Dielectric" at 11622.04,7682.73 h24
  text "Dielectric" at 11993.21,7682.73 h24
  text "Dielectric" at 12470.74,7682.73 h24
  text "Dielectric" at 12841.91,7682.73 h24
  text "Name" at 10305,7634.73 h24
  text "Document" at 10952.48,7634.73 h24
  text "Thickness" at 11267.67,7634.73 h24
  text "Height" at 11622.04,7634.73 h24
  text "Material" at 11993.21,7634.73 h24
  text "Constant" at 12470.74,7634.73 h24
  text "Type" at 12841.91,7634.73 h24
  text "Top Solder Mask" at 10305,7547.46 h34
  text "(.GTS)" at 10952.48,7547.46 h34
  text "0.4mil" at 11622.04,7547.46 h34
  text "Solder Resist" at 11993.21,7547.46 h34
  text "3.50" at 12470.74,7547.46 h34
  text "Top Layer" at 10305,7413.71 h34
  text "(.GTL)" at 10952.48,7413.71 h34
  text "2.8mil" at 11267.67,7413.71 h34
  text "59.2mil" at 11622.04,7346.83 h34
  text "FR-4 High Tg" at 11993.21,7346.83 h34
  text "4.80" at 12470.74,7346.83 h34
  text "Core" at 12841.91,7346.83 h34
  text "Bottom Layer" at 10305,7279.96 h34
  text "(.GBL)" at 10952.48,7279.96 h34
  text "2.8mil" at 11267.67,7279.96 h34
  text "Bottom Solder Mask" at 10305,7146.21 h34
  text "(.GBS)" at 10952.48,7146.21 h34
  text "0.4mil" at 11622.04,7146.21 h34
  text "Solder Resist" at 11993.21,7146.21 h34
  text "3.50" at 12470.74,7146.21 h34
M13 Component Bodies Top:
  text ".Layer_Name" at -358,-858.49 h60
M14 Component Bodies Bottom:
  text ".Layer_Name" at -358,-858.49 h60
M15 Courtyards Top:
  text ".Layer_Name" at -358,-858.49 h60
M16 Courtyards Bottom:
  text ".Layer_Name" at -358,-858.49 h60
Drill Drawing:
  text ".legend" at -914,3825 h60
  text "Drill Table" at -888.5,3719.5 h60
  text "FOR 10MIL DRILL +0/-10MIL" at -897,3587 h60
  text "FOR 12MIL DRILL +0/-12MIL" at -885,3482 h60
  text "FOR PTH DRILL +/-3MIL" at -885,3374 h60
  text "FOR NPTH DRILL +/-2MIL" at -890,3273 h60
  text ".Layer_Name" at -358,-858.49 h60

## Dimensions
0,0 to 3789.41,0 on M2 Board Dimensions
-935,-410.5 to 65,-410.5 on M2 Board Dimensions
0,0 to 0,3228.35 on M2 Board Dimensions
